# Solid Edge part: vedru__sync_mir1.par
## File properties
Author: KULL
Template: Iso Metric Part.par
Last saved by: KULL
Revision: 2
Application: Solid Edge
Accuracy: 0,990
Username: KULL
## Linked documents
vedru__sync.par
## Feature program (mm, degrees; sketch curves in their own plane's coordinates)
part copy "CopiedPart_1"
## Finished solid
Body 1: solid body, 3 faces, 4 edges, 4 vertices.
  Faces by surface: torus 2, spline 1
  Edges by curve: circle 2, intersection 2
Bounding box of the edges (mm; curved faces can reach further): 6.787 x 25.640 x 26.544, from (-6.7872, -79.3784, 14.3974) to (0, -53.7383, 40.9412).
Toroidal faces (ring radius, tube radius in mm): R5.8516 r1.2 x2
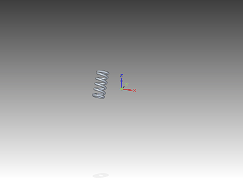
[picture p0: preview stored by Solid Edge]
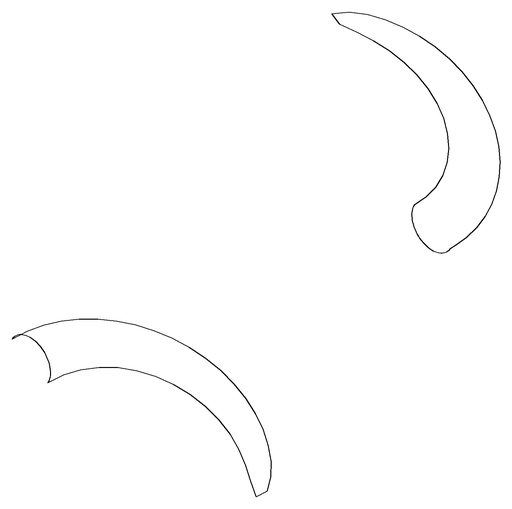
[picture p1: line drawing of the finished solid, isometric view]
